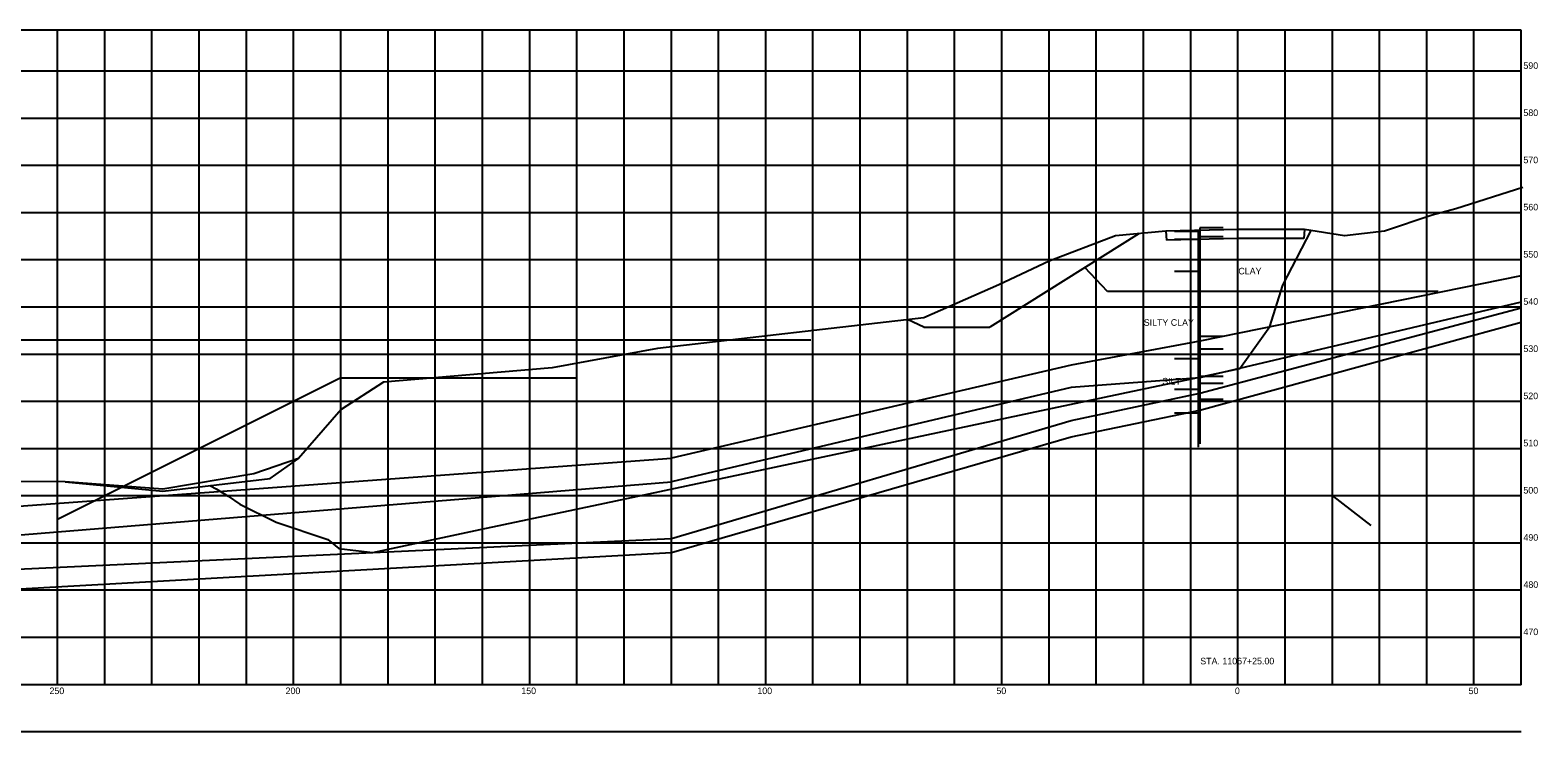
# Model space of a CAD drawing. Extents: x -64 to 1064, y -32 to 640.
# Drawn here: x 744.2 to 1063.5, y 450 to 598.7 of the extents above; entities that cross this region are included whole.
import ezdxf

# ---------------------------------------------------------------- set-up
doc = ezdxf.new("R2010")
doc.units = 0
for name, color, linetype in [('GT_Project_Soil_Boring', 7, 'Continuous'), ('GT_Project_Soil_Layers', 7, 'Continuous'), ('GT_X_Shear_Surface', 7, 'Continuous'), ('SC_Scratch1', 7, 'Continuous'), ('SH_Major_Grid_Line', 7, 'Continuous'), ('SH_Text', 7, 'Continuous')]:
    doc.layers.add(name, color=color, linetype=linetype)

msp = doc.modelspace()

# ---------------------------------------------------------------- linework, layer by layer
at = {"layer": 'GT_Project_Soil_Boring'}
for p, q in [((986.6, 556.1), (991.6, 556.1)), ((991.6, 556.1), (991.6, 510.33)), ((991.9, 556.8), (991.9, 511.01)), ((996.9, 556.8), (991.9, 556.8)), ((986.6, 554.4), (991.6, 554.4)), ((996.9, 554.9), (991.9, 554.9)), ((986.6, 547.6), (991.6, 547.6)), ((996.9, 543.3), (991.9, 543.3)), ((996.9, 533.8), (991.9, 533.8)), ((996.9, 531.1), (991.9, 531.1)), ((986.6, 529.1), (991.6, 529.1)), ((996.9, 525.3), (991.9, 525.3)), ((996.9, 523.8), (991.9, 523.8)), ((986.6, 522.6), (991.6, 522.6))]:
    msp.add_line(p, q, dxfattribs=at)
at = {"layer": 'GT_Project_Soil_Layers'}
for p, q in [((984.75, 556.1), (984.85, 554.21)), ((1014.08, 556.47), (1013.98, 554.57)), ((979.05, 555.59), (947.47, 535.79)), ((972.41, 543.3), (967.61, 548.42)), ((1042.39, 543.3), (972.41, 543.3)), ((933.5, 535.79), (930, 537.39)), ((933.5, 535.79), (947.47, 535.79)), ((986.6, 517.6), (991.6, 517.6)), ((996.9, 520.4), (991.9, 520.4)), ((660, 491.84), (880, 508)), ((660, 485.1), (880, 503)), ((660, 480.69), (880, 491)), ((660, 475.69), (880, 488))]:
    msp.add_line(p, q, dxfattribs=at)
for points in [[(1014.08, 556.47), (1000, 556.45), (984.75, 556.1)], [(1013.98, 554.57), (1000, 554.55), (984.85, 554.21)], [(1060, 546.61), (991.9, 532.8), (964.7, 527.7), (880, 508)], [(1060, 541.07), (991.9, 525), (964.7, 523), (880, 503)], [(880, 491), (964.7, 516), (991.9, 521.8), (1060, 539.88)], [(880, 488), (964.7, 512.5), (991.9, 518.2), (1060, 536.8)]]:
    msp.add_lwpolyline(points, dxfattribs=at)
at = {"layer": 'GT_X_Shear_Surface'}
msp.add_lwpolyline([(782.23, 502.18), (783.56, 501.53), (786.1, 499.94), (788.6, 498.28), (796.3, 494.41), (807.26, 490.77), (809.6, 488.89), (816.8, 488.04), (839.5, 492.86), (865.9, 498.46), (960.7, 518.57), (979.1, 522.48), (990.51, 524.9), (1000.43, 527), (1006.78, 535.89), (1009.49, 544.63), (1015.48, 556.27)], dxfattribs=at)
at = {"layer": 'SC_Scratch1'}
for p, q in [((909.57, 533), (628.77, 533)), ((810, 525), (750, 495)), ((810, 525), (860, 525)), ((1020, 500), (1028.17, 493.74))]:
    msp.add_line(p, q, dxfattribs=at)
for points in [[(1060.34, 565.34), (1046.19, 560.86), (1041.14, 559.51), (1031.04, 556.08), (1022.54, 555.09), (1014.08, 556.47), (1000.1, 556.46), (984.75, 556.1), (974.05, 555.14), (960.03, 549.74), (949.37, 544.71), (933.45, 537.77), (877.04, 531.23), (854.76, 527.13), (819.06, 524.1), (810.1, 518.28), (801.03, 507.96), (791.54, 504.68), (772.26, 501.45), (751.61, 503.01), (741.55, 503.07)], [(751.61, 503.01), (772.3, 501), (795, 503.7), (801.03, 507.96)]]:
    msp.add_lwpolyline(points, dxfattribs=at)
at = {"layer": 'SH_Major_Grid_Line'}
for p, q in [((1060, 598.71), (660, 598.71)), ((750, 460), (750, 598.71)), ((760, 460), (760, 598.71)), ((770, 460), (770, 598.71)), ((780, 460), (780, 598.71)), ((790, 460), (790, 598.71)), ((800, 460), (800, 598.71)), ((810, 460), (810, 598.71)), ((820, 460), (820, 598.71)), ((830, 460), (830, 598.71)), ((840, 460), (840, 598.71)), ((850, 460), (850, 598.71)), ((860, 460), (860, 598.71)), ((870, 460), (870, 598.71)), ((880, 460), (880, 598.71)), ((890, 460), (890, 598.71)), ((900, 460), (900, 598.71)), ((910, 460), (910, 598.71)), ((920, 460), (920, 598.71)), ((930, 460), (930, 598.71)), ((940, 460), (940, 598.71)), ((950, 460), (950, 598.71)), ((960, 460), (960, 598.71)), ((970, 460), (970, 598.71)), ((980, 460), (980, 598.71)), ((990, 460), (990, 598.71)), ((1000, 460), (1000, 598.71)), ((1010, 460), (1010, 598.71)), ((1020, 460), (1020, 598.71)), ((1030, 460), (1030, 598.71)), ((1040, 460), (1040, 598.71)), ((1050, 460), (1050, 598.71)), ((1060, 460), (1060, 598.71)), ((1060, 590), (660, 590)), ((1060, 580), (660, 580)), ((1060, 570), (660, 570)), ((1060, 560), (660, 560)), ((1060, 550), (660, 550)), ((1060, 540), (660, 540)), ((1060, 530), (660, 530)), ((1060, 520), (660, 520)), ((1060, 510), (660, 510)), ((1060, 500), (660, 500)), ((1060, 490), (660, 490)), ((1060, 480), (660, 480)), ((1060, 470), (660, 470)), ((1060, 460), (660, 460)), ((1060, 450), (660, 450))]:
    msp.add_line(p, q, dxfattribs=at)

# ---------------------------------------------------------------- texts
at = {"layer": 'GT_Project_Soil_Boring'}
for s, p in [('CLAY', (1000.1, 546.94)), ('SILTY CLAY', (980.06, 536.05)), ('SILT', (983.96, 523.61))]:
    msp.add_text(s, height=1.4, dxfattribs=at).set_placement(p)
at = {"layer": 'SH_Text'}
for s, p in [('590', (1060.47, 590.5)), ('580', (1060.47, 580.5)), ('570', (1060.47, 570.5)), ('560', (1060.47, 560.5)), ('550', (1060.47, 550.5)), ('540', (1060.47, 540.5)), ('530', (1060.47, 530.5)), ('520', (1060.47, 520.5)), ('510', (1060.47, 510.5)), ('500', (1060.47, 500.5)), ('490', (1060.48, 490.5)), ('480', (1060.48, 480.5)), ('470', (1060.48, 470.5)), ('STA. 11067+25.00', (992.03, 464.3)), ('250', (748.29, 458)), ('200', (798.29, 458)), ('150', (848.22, 458)), ('100', (898.22, 458)), ('50', (948.85, 458)), ('0', (999.36, 458)), ('50', (1048.85, 458))]:
    msp.add_text(s, height=1.4, dxfattribs=at).set_placement(p)

doc.saveas('drawing.dxf')
